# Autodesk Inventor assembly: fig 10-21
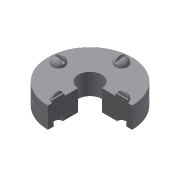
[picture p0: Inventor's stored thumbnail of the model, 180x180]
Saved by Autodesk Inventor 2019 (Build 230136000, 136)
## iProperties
Shininess: 64.0
Angle Display Precision: 2
Document Length Units: 11269
Document Angle Units: 11279
Document Time Units: 11290
Document Mass Units: 11283
Document Length Units Precision: 3
Document Angle Units Precision: 2
Created: 2002-02
Part Number: fig 10-21
Document SubType Name: Assembly
Designer: ***
Density: 0.0
Volumn: 0.0
Area: 0.0
PropertySet Name: Model Information
Control State: 0
Master: False
Checked Out: False
Author: ***
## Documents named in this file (3)
- E:\_Deepak\Inventor\Projects\Autodesk Inventor_2019_Project\Resources\Inventor_2018_Part\c10_Inv_2019_prt\fig 10-21.iam
- E:\_Deepak\Inventor\Projects\Autodesk Inventor_2019_Project\Resources\Inventor_2018_Part\c10_Inv_2019_prt\Screw.ipt
- E:\_Deepak\Inventor\Projects\Autodesk Inventor_2019_Project\Resources\Inventor_2018_Part\c10_Inv_2019_prt\test.ipt
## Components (6 placed, 2 different names)
1. test:1 — Insert:1, Insert:2
2. test:2 — Insert:1
3. Screw:1 — Angle:1, Insert:2
4. Screw:11
5. Screw:12
6. Screw:13
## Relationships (3: Insert 2, Angle 1)
- Insert:1: test:1 ↔ test:2
- Angle:1: Screw:1
- Insert:2: test:1 ↔ Screw:1
